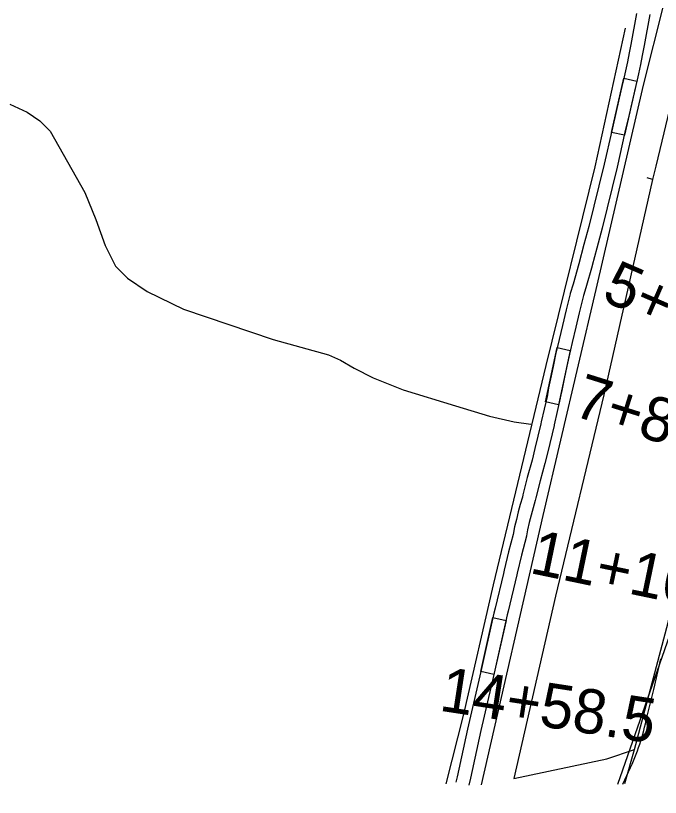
# Model space of a CAD drawing. Extents: x 3172297 to 3210190, y 958463 to 983887.
# Drawn here: x 3184693 to 3186145, y 963866 to 965627 of the extents above; entities that cross this region are included whole.
import ezdxf

# ---------------------------------------------------------------- set-up
doc = ezdxf.new("R2010")
doc.units = 0
for name, color, linetype in [('V-LEVE-TOET', 7, 'Continuous'), ('V-RIVR-RANG', 7, 'Continuous'), ('V-ROAD-CNTR', 7, 'Continuous'), ('V-TOPO-BNDY', 7, 'Continuous'), ('V-TOPO-SHOR', 7, 'Continuous')]:
    doc.layers.add(name, color=color, linetype=linetype)

msp = doc.modelspace()

# ---------------------------------------------------------------- linework, layer by layer
at = {"layer": 'V-LEVE-TOET'}
msp.add_lwpolyline([(3186060.4, 963895.9), (3186077.7, 963933.7), (3186077.7, 963933.7), (3186081, 963941), (3186084.2, 963948.3), (3186087.3, 963955.7), (3186090.3, 963963.1), (3186093.1, 963970.6), (3186095.8, 963978.1), (3186098.4, 963985.7), (3186100.8, 963993.3), (3186103.2, 964001), (3186105.3, 964008.7), (3186107.4, 964016.4), (3186109.3, 964024.2), (3186111, 964032), (3186112.7, 964039.8), (3186112.8, 964040.3), (3186112.8, 964040.3), (3186129.9, 964109), (3186146, 964178)], dxfattribs=at)
at = {"layer": 'V-ROAD-CNTR'}
for points in [[(3186090.8, 965632.2), (3186078.2, 965562.3), (3186078.2, 965562.3), (3186074.7, 965543.1), (3186070.8, 965522.8), (3186066.4, 965502.5), (3186061.8, 965482.2), (3186059.7, 965473.8), (3186045.5, 965411.1), (3186035.2, 965367.8), (3186035.2, 965367.7), (3186018.1, 965292.6), (3186006.2, 965243.6), (3186006.2, 965243.6), (3185983.6, 965152.1), (3185983.6, 965152.3), (3185972.5, 965111.2), (3185961.6, 965067.8), (3185961.6, 965068.1), (3185948.2, 965022.4), (3185942.1, 965000.8), (3185942.1, 965000.6), (3185933, 964964.6), (3185924.5, 964929), (3185924.5, 964929), (3185916.7, 964897.5), (3185909.1, 964863.9), (3185904, 964840.3), (3185904, 964840.3), (3185898.6, 964815.3), (3185893.2, 964788.5), (3185889.6, 964768.6), (3185889.6, 964768.9), (3185876.7, 964711.9), (3185875.6, 964707.2), (3185875.6, 964707.2), (3185862.3, 964651.6), (3185855.9, 964626), (3185845.3, 964587), (3185835.3, 964547.7), (3185834.1, 964542.4), (3185829.4, 964526.1), (3185824.9, 964509.2), (3185820.7, 964492.3), (3185816.7, 964475.2), (3185813.1, 964458.2), (3185813.1, 964458.5), (3185803.1, 964419.2), (3185793.2, 964377.8), (3185791.6, 964370.5), (3185791.6, 964370.6), (3185772.8, 964292.4), (3185770.1, 964280.7), (3185770.1, 964280.7), (3185740.6, 964149.3), (3185740.6, 964149.3), (3185710.8, 964020.1), (3185710.8, 964020), (3185687.2, 963912.5), (3185687.2, 963912.5), (3185684.5, 963900)], [(3186120.8, 965629.5), (3186108.2, 965559.7), (3186108.2, 965559.7), (3186104.2, 965537.6), (3186100.2, 965516.7), (3186095.7, 965496), (3186090.9, 965475.3), (3186088.9, 965466.9), (3186074.7, 965404.3), (3186065.2, 965364.3), (3186065.2, 965364.4), (3186047.3, 965285.8), (3186036.2, 965240), (3186036.2, 965239.9), (3186013.6, 965148.5), (3186013.6, 965148.3), (3186001.6, 965103.6), (3185991.6, 965064.1), (3185991.6, 965063.8), (3185977, 965014.1), (3185972.1, 964996.6), (3185972.1, 964996.8), (3185962.1, 964957.5), (3185954.5, 964925.5), (3185954.5, 964925.4), (3185945.9, 964890.6), (3185938.4, 964857.5), (3185934, 964837.1), (3185934, 964837.1), (3185928, 964809.2), (3185922.7, 964782.8), (3185919.6, 964765.8), (3185919.6, 964765.5), (3185905.9, 964705.2), (3185905.6, 964703.7), (3185905.6, 964703.7), (3185891.4, 964644.4), (3185884.9, 964618.4), (3185874.3, 964579.4), (3185864.5, 964540.5), (3185863.1, 964534.8), (3185858.3, 964518.1), (3185853.9, 964501.7), (3185849.8, 964485.3), (3185846, 964468.7), (3185843.1, 964455), (3185843.1, 964454.7), (3185832.2, 964412), (3185822.4, 964370.9), (3185821.6, 964367.2), (3185821.6, 964367.1), (3185802, 964285.6), (3185800.1, 964277.3), (3185800.1, 964277.3), (3185770.6, 964146), (3185770.6, 964145.9), (3185740.8, 964016.6), (3185740.8, 964016.7), (3185717.2, 963909.3), (3185717.2, 963909.3), (3185713.8, 963893.6)]]:
    msp.add_lwpolyline(points, dxfattribs=at)
for points in [[(3186091.7, 965479.3), (3186064.1, 965357.4), (3186034.8, 965364), (3186062.4, 965485.9)], [(3185941.8, 964872.8), (3185915.2, 964750.6), (3185885.9, 964757), (3185912.5, 964879.2)], [(3185797.3, 964264.7), (3185769.9, 964142.8), (3185740.6, 964149.4), (3185768, 964271.3)]]:
    msp.add_lwpolyline(points, close=True, dxfattribs=at)
at = {"layer": 'V-TOPO-BNDY'}
msp.add_lwpolyline([(3186048.8, 963896), (3186249.6, 964470), (3198733.3, 964517.6), (3198114.7, 963866.1)], dxfattribs=at)
at = {"layer": 'V-TOPO-SHOR'}
for points in [[(3185742, 963894.7), (3185881, 964501.4), (3186000.1, 965010), (3186106.6, 965470.4), (3186198.5, 965834.4), (3186214.7, 965870.1), (3186221.8, 965880.8), (3186238, 965896.8), (3186250.5, 965907.5)], [(3186498.1, 965658.7), (3186457.1, 965708.8), (3186410.8, 965751.8), (3186355.6, 965807.3), (3186332.4, 965830.5), (3186327.1, 965832.3), (3186318.1, 965830.6), (3186318.1, 965821.6), (3186311, 965814.5), (3186289.5, 965803.8), (3186269.9, 965798.5), (3186259.1, 965791.4), (3186250.2, 965778.9), (3186174.4, 965454.2), (3186134.7, 965288.2), (3186127.5, 965257.9), (3186115, 965261.5)], [(3186065.8, 965599.1), (3185997.2, 965286.8), (3185887.2, 964838.9), (3185768.1, 964344.6), (3185701.3, 964053.7), (3185661.6, 963896.7)], [(3184679.8, 965427.5), (3184719.1, 965409.6), (3184747.6, 965389.8), (3184770.7, 965366.6), (3184849, 965228.9), (3184873.8, 965168.1), (3184895.1, 965109.2), (3184918.2, 965062.7), (3184944.9, 965035.8), (3184989.5, 965005.4), (3185071.5, 964965.9), (3185273.1, 964897.5), (3185398, 964863.3), (3185424.7, 964850.7), (3185455.1, 964832.8), (3185497.9, 964811.3), (3185565.6, 964784.3), (3185683.4, 964748.3), (3185760.1, 964724.9), (3185815.4, 964712.3), (3185852.9, 964706.8)], [(3186127.5, 965257.9), (3186017.3, 964772.5), (3185909.1, 964319.2), (3185815.2, 963908.8), (3186024.2, 963952.9), (3186086.8, 963974.2)], [(3186065.2, 963897.5), (3186086.8, 963974.2), (3186162.5, 964259.7), (3186196.8, 964423.9), (3186220.3, 964522), (3186236.4, 964552.3)]]:
    msp.add_lwpolyline(points, dxfattribs=at)

# ---------------------------------------------------------------- texts
at = {"layer": 'V-RIVR-RANG'}
for s, rotation, p in [('5+53.1', 336.5444, (3186009.5, 964987)), ('7+81.9', 342.5625, (3185944.5, 964727)), ('11+10.2', 348.2506, (3185847.9, 964372)), ('14+58.5', 351.2744, (3185644.8, 964061.8))]:
    msp.add_text(s, height=100, rotation=rotation, dxfattribs=at).set_placement(p)

doc.saveas('drawing.dxf')
